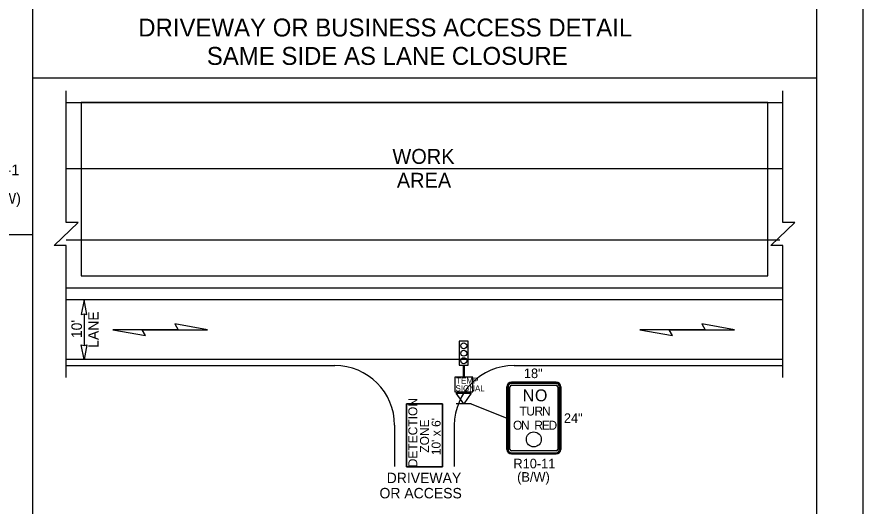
# Model space of a CAD drawing. Extents: x 99977 to 100176, y 99905 to 100011.
# Drawn here: x 100050.4 to 100056.06, y 100004.3 to 100007.58 of the extents above; entities that cross this region are included whole.
import ezdxf

# ---------------------------------------------------------------- set-up
doc = ezdxf.new("R2010")
doc.units = 0
for name, color, linetype in [('Default', 7, 'Continuous'), ('RD_ED_DrivewayEdge', 7, 'Continuous'), ('RD_ED_ShoulderPavedEdge', 7, 'Continuous'), ('RD_MK_LineEdgeWhite', 7, 'Continuous'), ('RD_MK_LineSkipCenter', 7, 'Continuous'), ('SH_DE_DetailHeading2Text', 7, 'Continuous'), ('SH_GI_PlotLimits', 7, 'Continuous'), ('SH_GI_SheetBorder', 7, 'Continuous'), ('TR_SN_ConstructionSigns', 7, 'Continuous'), ('TR_WZ_PortableSignMountBlk-Wht', 7, 'Continuous'), ('TR_WZ_TempSignal', 7, 'Continuous'), ('TR_WZ_WorkAreaLabel', 7, 'Continuous'), ('TR_WZ_WorkZoneDetails', 7, 'Continuous'), ('TR_WZ_WorkZoneTextCurrent', 7, 'Continuous')]:
    doc.layers.add(name, color=color, linetype=linetype)

msp = doc.modelspace()

# ---------------------------------------------------------------- linework, layer by layer
at = {"layer": 'Default'}
msp.add_circle((100053.8574, 100004.7505), 0.05, dxfattribs=at)
at = {"layer": 'RD_ED_DrivewayEdge'}
for p, q in [((100052.925, 100004.845), (100052.925, 100004.5696)), ((100053.325, 100004.845), (100053.325, 100004.5696))]:
    msp.add_line(p, q, dxfattribs=at)
for centre, start, end in [((100052.525, 100004.845), 0, 90), ((100053.725, 100004.845), 90, 180)]:
    msp.add_arc(centre, 0.4, start, end, dxfattribs=at)
at = {"layer": 'RD_ED_ShoulderPavedEdge'}
for p, q in [((100050.725, 100007.005), (100055.525, 100007.005)), ((100050.725, 100005.245), (100052.525, 100005.245)), ((100050.725, 100005.245), (100052.525, 100005.245)), ((100053.725, 100005.245), (100055.525, 100005.245)), ((100053.725, 100005.245), (100055.525, 100005.245))]:
    msp.add_line(p, q, dxfattribs=at)
at = {"layer": 'RD_MK_LineEdgeWhite'}
for p, q in [((100050.725, 100006.565), (100055.525, 100006.565)), ((100055.525, 100005.685), (100050.725, 100005.685)), ((100055.525, 100005.285), (100050.725, 100005.285))]:
    msp.add_line(p, q, dxfattribs=at)
at = {"layer": 'RD_MK_LineSkipCenter'}
msp.add_lwpolyline([(100055.5043, 100006.085), (100050.725, 100006.085)], dxfattribs=at)
at = {"layer": 'SH_GI_PlotLimits'}
msp.add_lwpolyline([(100039.0625, 99999.6875), (100056.0625, 99999.6875), (100056.0625, 100010.6875), (100039.0625, 100010.6875)], close=True, dxfattribs=at)
at = {"layer": 'SH_GI_SheetBorder'}
msp.add_line((100055.75, 100010.375), (100055.75, 100000), dxfattribs=at)
at = {"layer": 'TR_SN_ConstructionSigns'}
for p, q in [((100053.7074, 100005.133), (100054.0074, 100005.133)), ((100054.0074, 100005.133), (100053.7074, 100005.133)), ((100054.0074, 100005.133), (100053.7074, 100005.133)), ((100054.0074, 100005.1255), (100053.7074, 100005.1255)), ((100053.6774, 100004.683), (100053.6774, 100005.103)), ((100053.6774, 100005.103), (100053.6774, 100004.683)), ((100053.6774, 100005.103), (100053.6774, 100004.683)), ((100053.6849, 100005.103), (100053.6849, 100004.683)), ((100053.6974, 100004.683), (100053.6974, 100005.103)), ((100053.7074, 100005.113), (100054.0074, 100005.113)), ((100054.0174, 100005.103), (100054.0174, 100004.683)), ((100054.0299, 100004.683), (100054.0299, 100005.103)), ((100054.0374, 100005.103), (100054.0374, 100004.683)), ((100054.0374, 100004.683), (100054.0374, 100005.103)), ((100054.0374, 100004.683), (100054.0374, 100005.103)), ((100054.0074, 100004.673), (100053.7074, 100004.673)), ((100053.7074, 100004.6605), (100054.0074, 100004.6605)), ((100054.0074, 100004.653), (100053.7074, 100004.653)), ((100053.7074, 100004.653), (100054.0074, 100004.653)), ((100053.7074, 100004.653), (100054.0074, 100004.653))]:
    msp.add_line(p, q, dxfattribs=at)
for centre, radius, start, end in [((100053.7074, 100005.103), 0.03, 90, 180), ((100053.7074, 100005.103), 0.03, 90, 180), ((100053.7074, 100005.103), 0.03, 90, 180), ((100053.7074, 100005.103), 0.0225, 90, 180), ((100054.0074, 100005.103), 0.03, 0, 90), ((100054.0074, 100005.103), 0.03, 0, 90), ((100054.0074, 100005.103), 0.03, 0, 90), ((100054.0074, 100005.103), 0.0225, 0, 90), ((100053.7074, 100005.103), 0.01, 90, 180), ((100054.0074, 100005.103), 0.01, 0, 90), ((100053.7074, 100004.683), 0.03, 180, 270), ((100053.7074, 100004.683), 0.03, 180, 270), ((100053.7074, 100004.683), 0.03, 180, 270), ((100053.7074, 100004.683), 0.0225, 180, 270), ((100053.7074, 100004.683), 0.01, 180, 270), ((100054.0074, 100004.683), 0.03, 270, 0), ((100054.0074, 100004.683), 0.03, 270, 0), ((100054.0074, 100004.683), 0.0225, 270, 0), ((100054.0074, 100004.683), 0.01, 270, 0), ((100054.0074, 100004.683), 0.03, 270, 0)]:
    msp.add_arc(centre, radius, start, end, dxfattribs=at)
at = {"layer": 'TR_WZ_PortableSignMountBlk-Wht'}
msp.add_line((100053.4383, 100004.9878), (100053.3383, 100004.9878), dxfattribs=at)
msp.add_lwpolyline([(100053.3884, 100004.9878), (100053.3383, 100005.0596), (100053.4383, 100005.0596)], close=True, dxfattribs=at)
at = {"layer": 'TR_WZ_TempSignal'}
for p, q in [((100053.4182, 100005.4071), (100053.3583, 100005.4071)), ((100053.3583, 100005.4071), (100053.3583, 100005.2474)), ((100053.4182, 100005.2474), (100053.4182, 100005.4071)), ((100053.3583, 100005.2474), (100053.4182, 100005.2474)), ((100053.4483, 100005.1674), (100053.3283, 100005.1674)), ((100053.3283, 100005.1674), (100053.3283, 100005.1229)), ((100053.3283, 100005.1229), (100053.3283, 100005.1141)), ((100053.4483, 100005.0696), (100053.4483, 100005.1674)), ((100053.3283, 100005.1141), (100053.3283, 100005.0696)), ((100053.3283, 100005.0696), (100053.4483, 100005.0696))]:
    msp.add_line(p, q, dxfattribs=at)
for points in [[(100053.4182, 100005.4071), (100053.3583, 100005.4071), (100053.3583, 100005.2474), (100053.4182, 100005.2474), (100053.4182, 100005.4071)], [(100053.4483, 100005.1674), (100053.3283, 100005.1674), (100053.3283, 100005.0696), (100053.4483, 100005.0696), (100053.4483, 100005.1674)]]:
    msp.add_lwpolyline(points, dxfattribs=at)
msp.add_lwpolyline([(100053.3858, 100005.2474), (100053.3908, 100005.2474), (100053.3908, 100005.1674), (100053.3858, 100005.1674)], close=True, dxfattribs=at)
for centre in [(100053.3883, 100005.3772), (100053.3883, 100005.3772), (100053.3883, 100005.3273), (100053.3883, 100005.3273), (100053.3883, 100005.2773), (100053.3883, 100005.2773)]:
    msp.add_circle(centre, 0.02, dxfattribs=at)
at = {"layer": 'TR_WZ_WorkZoneDetails'}
for p, q in [((100050.5, 100010.275), (100050.5, 100001.2259)), ((100055.75, 100007.1677), (100050.5, 100007.1677)), ((100050.5, 100006.1205), (100045.25, 100006.1205)), ((100050.725, 100005.765), (100055.525, 100005.765)), ((100050.845, 100005.5913), (100050.845, 100005.3787)), ((100051.4761, 100005.485), (100051.235, 100005.485)), ((100051.235, 100005.485), (100051.4761, 100005.485)), ((100055.0052, 100005.485), (100054.7641, 100005.485)), ((100054.7641, 100005.485), (100055.0052, 100005.485)), ((100053.4383, 100004.9878), (100053.6774, 100004.893))]:
    msp.add_line(p, q, dxfattribs=at)
for points in [[(100050.725, 100005.165), (100050.725, 100006.0476), (100050.645, 100006.0476), (100050.805, 100006.2024), (100050.725, 100006.2024), (100050.725, 100007.085)], [(100055.525, 100005.165), (100055.525, 100006.0476), (100055.445, 100006.0476), (100055.605, 100006.2024), (100055.525, 100006.2024), (100055.525, 100007.085)], [(100053.005, 100004.5678), (100053.005, 100004.9878), (100053.245, 100004.9878), (100053.245, 100004.5678), (100053.005, 100004.5678)], [(100053.245, 100004.5678), (100053.245, 100004.9878), (100053.005, 100004.9878), (100053.005, 100004.5678), (100053.245, 100004.5678)]]:
    msp.add_lwpolyline(points, dxfattribs=at)
for points in [[(100050.825, 100007.005), (100050.825, 100005.845), (100055.425, 100005.845), (100055.425, 100007.005)], [(100050.845, 100005.685), (100050.8257, 100005.5867), (100050.845, 100005.5913), (100050.8643, 100005.5867)], [(100051.6727, 100005.485), (100051.4539, 100005.5236), (100051.4761, 100005.485)], [(100055.2017, 100005.485), (100054.9829, 100005.5236), (100055.0052, 100005.485)], [(100051.0385, 100005.485), (100051.2573, 100005.4464), (100051.235, 100005.485)], [(100054.5675, 100005.485), (100054.7864, 100005.4464), (100054.7641, 100005.485)], [(100050.845, 100005.285), (100050.8257, 100005.3833), (100050.845, 100005.3787), (100050.8643, 100005.3833)]]:
    msp.add_lwpolyline(points, close=True, dxfattribs=at)

# ---------------------------------------------------------------- texts
at = {"layer": 'Default'}
for s, height, p in [('N', 0.08, (100053.7826, 100005.0055)), ('O', 0.08, (100053.865, 100005.0055)), ('T', 0.06, (100053.7613, 100004.9105)), ('U', 0.06, (100053.8072, 100004.9105)), ('R', 0.06, (100053.862, 100004.9105)), ('N', 0.06, (100053.9127, 100004.9105)), ('O', 0.06, (100053.718, 100004.8155)), ('N', 0.06, (100053.7714, 100004.8155)), ('R', 0.06, (100053.8613, 100004.8155)), ('E', 0.06, (100053.9105, 100004.8155)), ('D', 0.06, (100053.956, 100004.8155))]:
    msp.add_text(s, height=height, dxfattribs=at).set_placement(p)
at = {"layer": 'SH_DE_DetailHeading2Text'}
for s, p in [('DRIVEWAY OR BUSINESS ACCESS DETAIL', (100051.2082, 100007.4477)), ('SAME SIDE AS LANE CLOSURE', (100051.6677, 100007.2577))]:
    msp.add_text(s, height=0.12, rotation=360, dxfattribs=at).set_placement(p)
at = {"layer": 'TR_SN_ConstructionSigns'}
for s, p in [('18"', (100053.7909, 100005.161)), ('24"', (100054.0589, 100004.861)), ('R10-11', (100053.7209, 100004.557)), ('(B/W)', (100053.7458, 100004.4674))]:
    msp.add_text(s, height=0.064, rotation=360, dxfattribs=at).set_placement(p)
at = {"layer": 'TR_WZ_TempSignal'}
for s, p in [('TEMP', (100053.3377, 100005.1245)), ('SIGNAL', (100053.3327, 100005.0725))]:
    msp.add_text(s, height=0.04, dxfattribs=at).set_placement(p)
at = {"layer": 'TR_WZ_WorkAreaLabel'}
for s, p in [('WORK', (100052.9105, 100006.595)), ('AREA', (100052.9401, 100006.435))]:
    msp.add_text(s, height=0.1, rotation=360, dxfattribs=at).set_placement(p)
at = {"layer": 'TR_WZ_WorkZoneDetails'}
for s, height, rotation, p in [('R2-1', 0.072, 360, (100050.2029, 100006.5185)), ('(B/W)', 0.072, 360, (100050.1764, 100006.3283)), ('DETECTION', 0.06, 90, (100053.077, 100004.564)), ("10' x 6'", 0.06, 90, (100053.233, 100004.6448)), ('ZONE', 0.06, 90, (100053.155, 100004.6615))]:
    msp.add_text(s, height=height, rotation=rotation, dxfattribs=at).set_placement(p)
at = {"layer": 'TR_WZ_WorkZoneTextCurrent'}
for s, p in [('LANE', (100050.943, 100005.3635)), ("10'", (100050.831, 100005.4282))]:
    msp.add_text(s, height=0.07, rotation=90, dxfattribs=at).set_placement(p)
for s, p in [('DRIVEWAY', (100052.8721, 100004.4578)), ('OR ACCESS', (100052.8239, 100004.3558))]:
    msp.add_text(s, height=0.07, dxfattribs=at).set_placement(p)

doc.saveas('drawing.dxf')
